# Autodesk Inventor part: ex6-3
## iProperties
Author: Administrator
Created: 2001-09
Part Number: ex6-3
Document SubType Name: Modeling
Designer: Administrator
Control State: 0
Master: False
Checked Out: False
PropertySet Name: Design Tracking Control
Length Units: 11272
Angle Units: 11279
Time Units: 11290
Mass Units: 11286
Shininess: 3
Angle Display Precision: 2
Document Length Units: 11272
Document Angle Units: 11286
Document Time Units: 11279
Document Mass Units: 11290
Document Length Units Precision: 3
Document Angle Units Precision: 2
Compacted: False
PropertySet Name: _Private Model Information
Density: 0.0
Volumn: 0.0
Area: 0.0
PropertySet Name: Model Information
